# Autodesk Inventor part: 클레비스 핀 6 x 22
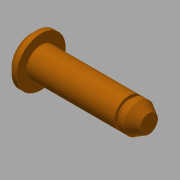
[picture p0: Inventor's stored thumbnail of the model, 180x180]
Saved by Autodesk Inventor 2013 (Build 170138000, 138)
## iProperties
IsCustomPart: 1
Created: 2017-08
Part Number: 클레비스 핀 6 x 22
Material: 강철
Description: 머리가 있는 클레비스 핀
Document SubType Name: Modeling
Standard: ISO 2341
Designer: mduedu
Standard Revision: Second edition 1986-11-01
Standards Organization: ISO
Language: ko-KR
Size Designation: B - 6 x 24
Categories: <MemberInstance><Categories><Category DisplayName="조임쇠" InternalName="e4da775c-781d-43d5-af7c-5136215cf5a6" Mnemonic="FSTN"><Category DisplayName="핀" InternalNa
Density: 7.85 g/cm^3
Author: mduedu
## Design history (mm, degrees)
sketch "스케치1"
  geometry: L1 (-2, 0)-(-2, 5); L2 (-2, 5)-(0, 5); L3 (0, 5)-(0, 3); L4 (0, 3)-(22, 3); L5 (22, 3)-(22, 0); L6 (-2, 0)-(22, 0); L7 (-7, 0)-(28, 0) reference; L8 (0, -1.96)-(0, 6.16) reference; C1 r 0.8 at (18.8, 0)
  constraints: 12 end point, 3 parallel, 2 collinear, 2 perpendicular, 1 centre point, 1 point on line, 1 vertical
  dimensions: "d0" = 6 diameter of L4 L6 (= NND); "d1" = 10 diameter of L2 L6 (= KOD); "d2" = 2 distance of L1.end L2.end (= KOH); "d3" = 22 distance of L3.end L4.end (= NLG); "d5" = 3.2 distance from line of L5 C1.centre (= DIST); "d6" = 1.6 diameter of C1 (= BOR)
revolve "본체" stored, may be unused: angle "d4" = 90 deg
workplane "Work Plane1"
node "작업 평면4"
sketch "스케치2"
  geometry: C1 r 3 at (0, 0) reference; C2 r 2.425 at (0, 0); 1 further point
  constraints: 1 centre point, 1 coincident
  dimensions: "d33" = 4.85 diameter of C2
extrude "돌출2" cut sketch "스케치2" distance "d34" = 0.7; taper "d35" = 0 deg
body "Solid1"
chamfer "모따기1" distance "d9" = 1 (= PHH2); stored, may be unused: angle "d10" = 45 deg (= FAWI2), second distance "d16" = 1 (= PHH2)
chamfer "모따기2" distance "d11" = 2 (= PHH1); stored, may be unused: angle "d12" = 30 deg (= FAWI1), second distance "d17" = 2 (= PHH1)
other parameters: "PHH1" = 2 [user parameter; used in 2 equation terms], "PHH2" = 1 [user parameter; used in 2 equation terms], "KOD" = 10 [user parameter; used in 1 equation term], "KOH" = 2 [user parameter; used in 1 equation term], "NND" = 6 [user parameter; used in 1 equation term], "FAWI1" = 30 deg [user parameter; used in 1 equation term], "FAWI2" = 45 deg [user parameter; used in 1 equation term], "DIST" = 3.2 [user parameter; used in 1 equation term], "BOR" = 1.6 [user parameter; used in 1 equation term], "NLG" = 22 [user parameter; used in 1 equation term], "d13" = 0, "d14" = 0, "d30" = 0, "d32" = 18
